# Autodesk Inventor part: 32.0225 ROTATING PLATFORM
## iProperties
Created: 2012-10
Part Number: 32.0225 ROTATING PLATFORM
Document SubType Name: Modeling
Designer: Administrator
Density: 1.4 g/cm^3
Material: PVC-U
Mass: 30.0959 g
Surface Area: 85.7378 cm^2
Volume: 21.497 cm^3
Author: Administrator
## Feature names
1. Base1
